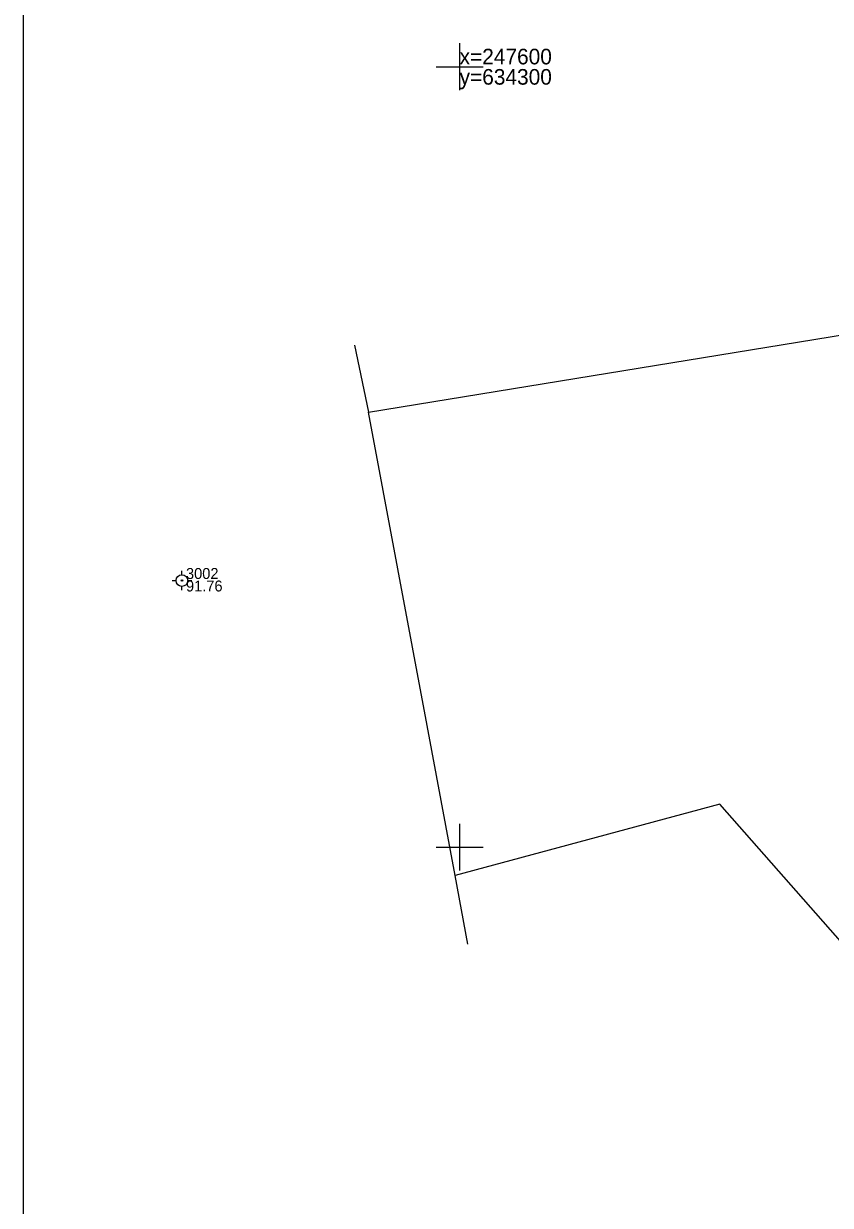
# Model space of a CAD drawing. Extents: x 634272 to 634544, y 247463 to 247653.
# Drawn here: x 634272.1 to 634323.8, y 247527 to 247602.8 of the extents above; entities that cross this region are included whole.
import ezdxf

# ---------------------------------------------------------------- set-up
doc = ezdxf.new("R2010")
doc.units = 0
for name, color, linetype in [('GEOD_ELEM_####_####_#', 7, 'Continuous'), ('GEOD_ELEM_####_TKST_#', 7, 'Continuous'), ('GEOD_KORD_####_TKST_#', 7, 'Continuous'), ('RAMI_PLAN_####_TKST_#', 7, 'Continuous'), ('ROBZ_PROJ_####_####_#', 7, 'Continuous'), ('ROBZ_UZMR_####_####_#', 7, 'Continuous')]:
    doc.layers.add(name, color=color, linetype=linetype)

msp = doc.modelspace()

# ---------------------------------------------------------------- linework, layer by layer
at = {"layer": 'GEOD_ELEM_####_####_#'}
for p, q in [((634300, 247601.5), (634300, 247600)), ((634298.5, 247600), (634300, 247600)), ((634300, 247600), (634300, 247598.5)), ((634300, 247600), (634301.5, 247600)), ((634282.214, 247567.455), (634282.214, 247567.705)), ((634281.589, 247567.08), (634281.839, 247567.08)), ((634282.589, 247567.08), (634282.839, 247567.08)), ((634282.214, 247566.455), (634282.214, 247566.705)), ((634300, 247551.5), (634300, 247550)), ((634298.5, 247550), (634300, 247550)), ((634300, 247550), (634300, 247548.5)), ((634300, 247550), (634301.5, 247550))]:
    msp.add_line(p, q, dxfattribs=at)
for radius in [0.375, 0.05]:
    msp.add_circle((634282.214, 247567.08), radius, dxfattribs=at)
at = {"layer": 'RAMI_PLAN_####_TKST_#'}
msp.add_lwpolyline([(634272.074, 247653.005), (634543.915, 247653.005), (634543.915, 247462.947), (634272.074, 247462.947)], close=True, dxfattribs=at)
at = {"layer": 'ROBZ_PROJ_####_####_#'}
for points in [[(634297.917, 247557.792), (634294.168, 247577.875)], [(634299.713, 247548.174), (634297.917, 247557.792)], [(634316.666, 247552.747), (634299.713, 247548.174)], [(634325.336, 247542.912), (634316.666, 247552.747)], [(634300.534, 247543.775), (634299.713, 247548.174)]]:
    msp.add_lwpolyline(points, dxfattribs=at)
at = {"layer": 'ROBZ_UZMR_####_####_#'}
for points in [[(634294.168, 247577.875), (634351.357, 247587.202)], [(634293.264, 247582.169), (634294.168, 247577.875)]]:
    msp.add_lwpolyline(points, dxfattribs=at)

# ---------------------------------------------------------------- texts
at = {"layer": 'GEOD_ELEM_####_TKST_#'}
for s, p in [(' 3002', (634282.214, 247567.181)), (' 91.76', (634282.214, 247566.38))]:
    msp.add_text(s, height=0.7, dxfattribs=at).set_placement(p)
at = {"layer": 'GEOD_KORD_####_TKST_#'}
for s, p in [('x=247600', (634300, 247600.15)), ('y=634300', (634300, 247598.85))]:
    msp.add_text(s, height=1, dxfattribs=at).set_placement(p)

doc.saveas('drawing.dxf')
